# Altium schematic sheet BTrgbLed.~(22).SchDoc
size A4
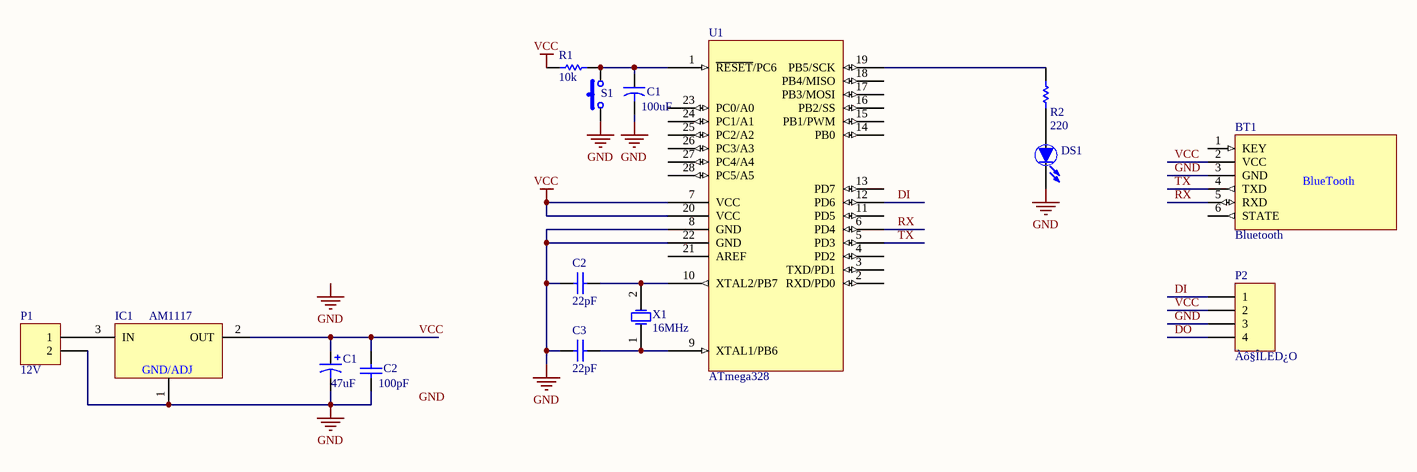
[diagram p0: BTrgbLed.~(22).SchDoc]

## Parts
(Parts that share a designator on the sheet are numbered #1, #2 ... from top to bottom, then left to right.)
BT1  Bluetooth  [Bluetooth]
C1#1  value 100uF  [CAPR5-4X5]  (hidden comment: Cap2)
C1#2  47uF  [RB7.6-15]
C2#1  22pF  [C200]
C2#2  value 100pF  [RAD-0.3]  (hidden comment: Cap)
C3  22pF  [C200]
DS1  TX-LED  [LED-3mm_G]  (value not drawn)
IC1  AM1117  [SOT-223]
P1  12V  [HDR1X2]
P2  Àô§ÎLED¿O  [HDR1X4]
R1  10k  [AXIAL-0.3]
R2  220  [AXIAL-0.3]
S1  SW-PB  [TACK6]  (value not drawn)
U1  ATmega328  [TEXTTOOL-28]
X1  16MHz  [XTAL4-8]

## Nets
GND: BT1.3(GND) C1#1.2 C1#2.2 C2#1.1 C2#2.2 C3.1 DS1.2(K) IC1.1(ADJ/GND) P1.2 P2.3 S1.1 U1.8(GND) U1.22(GND)
VCC: BT1.2(VCC) C1#2.1 C2#2.1 IC1.2(OUT) P2.2 R1.1 U1.7(VCC) U1.20(VCC)
DI: P2.1 U1.12(PD6)
DO: P2.4
RX: BT1.5(RXD) U1.6(PD4)
TX: BT1.4(TXD) U1.5(PD3)
NetC1#1_1: C1#1.1 R1.2 S1.2 U1.1(~{RESET}/PC6)
NetC2#1_2: C2#1.2 U1.10(XTAL2/PB7) X1.2(OSC2)
NetC3_2: C3.2 U1.9(XTAL1/PB6) X1.1(OSC1)
NetDS1_1: DS1.1(A) R2.1
NetIC1_3: IC1.3(IN) P1.1
NetR2_2: R2.2 U1.19(PB5/SCK)

Not connected (* = marked no-connect by the designer): BT1 1(KEY) 6(STATE); U1 2(RXD/PD0) 3(TXD/PD1) 4(PD2) 11(PD5) 13(PD7) 14(PB0) 15(PB1/PWM) 16(PB2/SS) 17(PB3/MOSI) 18(PB4/MISO) 21(AREF) 23(PC0/A0) 24(PC1/A1) 25(PC2/A2) 26(PC3/A3) 27(PC4/A4) 28(PC5/A5)

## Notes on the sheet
- Labels drawn without touching a wire or pin: GND

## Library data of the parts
C1#1 = Cap2: Capacitor
C1#2 = Cap Pol1: Polarized Capacitor (Radial)
C2#1 C2#2 C3 = Cap: Capacitor
DS1 = LED: Typical INFRARED GaAs LED
P1 = Header 2: Header, 2-Pin
P2 = Header 4: Header, 4-Pin
R1 R2 = Res: Resistor
S1 = SW-PB: Switch
U1 = ATmega328: Arduino
X1 = XTAL: Crystal Oscillator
